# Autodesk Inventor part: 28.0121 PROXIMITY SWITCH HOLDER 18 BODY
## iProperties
Created: 2007-05
Part Number: 28.0121 PROXIMITY SWITCH HOLDER 18 BODY
Document SubType Name: Modeling
Designer: Andy Moles
Material: Acetal Resin, Black
Density: 1.425 g/cm^3
Author: Andy Moles
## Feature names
1. Extrusion1
2. Extrusion2
3. Extrusion3
4. Extrusion4
5. Extrusion5
